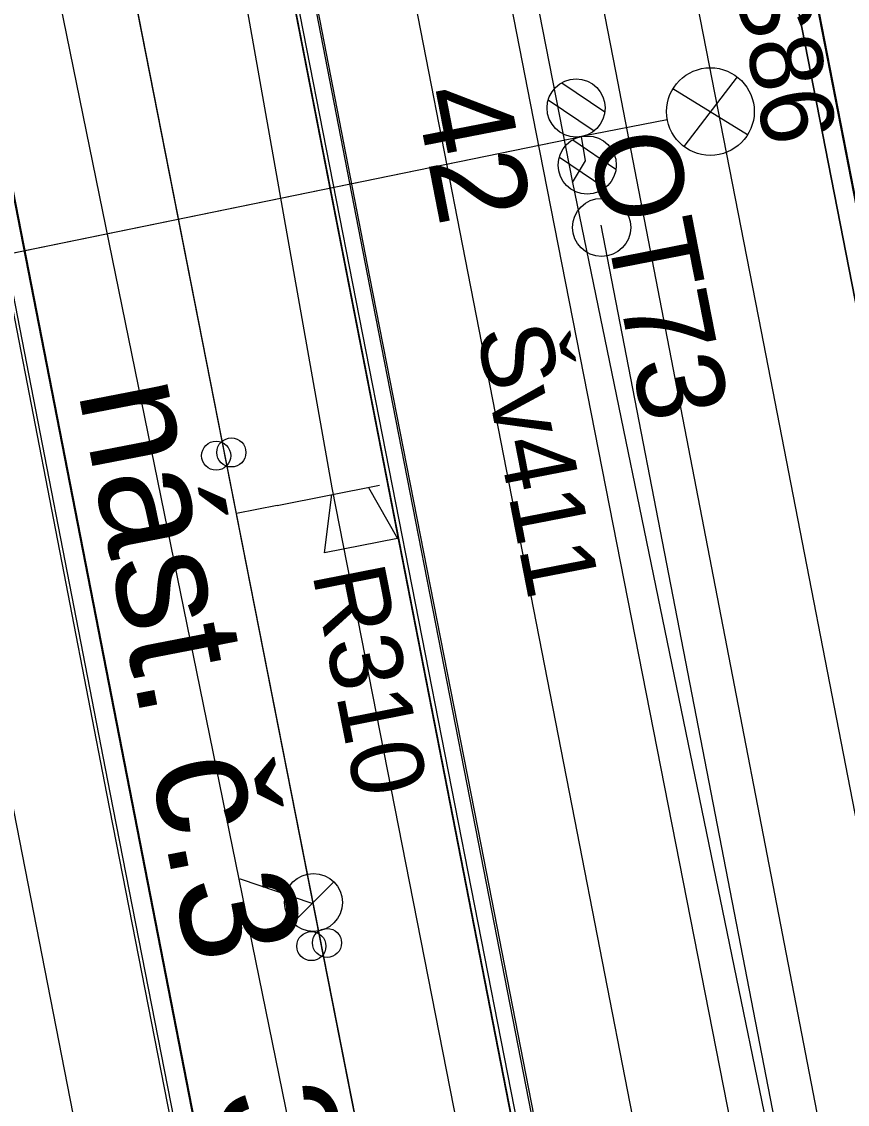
# Model space of a CAD drawing. Extents: x -545736 to -544888, y -1122892 to -1119128.
# Drawn here: x -545190.24 to -545176.05, y -1121835.11 to -1121816.49 of the extents above; entities that cross this region are included whole.
import ezdxf

# ---------------------------------------------------------------- set-up
doc = ezdxf.new("R2010")
doc.units = 0
for name, color, linetype in [('Podbarveni_Nastupiste', 7, 'Continuous'), ('Podbarveni_Zastreseni_Pozemni', 7, 'Continuous'), ('Vrstva 1 - Koleje', 7, 'Continuous'), ('Vrstva 11 - Trakce', 7, 'Continuous'), ('Vrstva 14_zastreseni a nastupiste', 7, 'Continuous'), ('Vrstva 16_plochy', 7, 'Continuous'), ('Vrstva 25', 7, 'Continuous'), ('Vrstva 26', 7, 'Continuous'), ('Vrstva 29 - sdelzar', 7, 'Continuous'), ('Vrstva 31', 7, 'Continuous'), ('Vrstva 33 - prvky sdelzar', 7, 'Continuous'), ('Vrstva 4 - Teren - stezky - prechody - plochy', 7, 'Continuous'), ('Vrstva 42', 7, 'Continuous'), ('Vrstva 43', 7, 'Continuous'), ('Vrstva 44', 7, 'Continuous')]:
    doc.layers.add(name, color=color, linetype=linetype)

msp = doc.modelspace()

# ---------------------------------------------------------------- linework, layer by layer
at = {"layer": 'Podbarveni_Nastupiste'}
for points in [[(-545217.368, -1121682.822), (-545215.446, -1121692.657), (-545213.545, -1121702.425), (-545211.641, -1121712.196), (-545209.721, -1121722.039), (-545207.816, -1121731.8), (-545205.906, -1121741.605), (-545203.994, -1121751.399), (-545202.093, -1121761.155), (-545200.179, -1121770.948), (-545198.277, -1121780.734), (-545196.359, -1121790.595), (-545195.979, -1121792.554), (-545194.455, -1121800.349), (-545192.535, -1121810.197), (-545190.626, -1121819.979), (-545188.728, -1121829.75), (-545186.804, -1121839.582), (-545184.9, -1121849.369), (-545182.993, -1121859.16)], [(-545176.664, -1121859.989), (-545178.574, -1121850.184), (-545180.481, -1121840.388), (-545182.39, -1121830.601), (-545184.299, -1121820.832), (-545186.202, -1121811.019), (-545188.114, -1121801.21), (-545190.028, -1121791.416), (-545191.936, -1121781.597), (-545194.23, -1121769.859), (-545195.758, -1121762.016), (-545197.67, -1121752.211), (-545199.585, -1121742.389), (-545201.492, -1121732.62), (-545203.329, -1121723.177), (-545205.298, -1121713.047), (-545207.216, -1121703.229), (-545209.127, -1121693.444), (-545211.033, -1121683.652)], [(-545187.331, -1121762.745), (-545185.417, -1121772.514), (-545183.504, -1121782.344), (-545181.6, -1121792.141), (-545179.691, -1121801.918), (-545177.789, -1121811.689), (-545175.868, -1121821.513), (-545173.955, -1121831.302)]]:
    msp.add_lwpolyline(points, dxfattribs=at)
at = {"layer": 'Podbarveni_Zastreseni_Pozemni'}
for points in [[(-545158.353, -1121955.704), (-545167.91, -1121906.688), (-545177.482, -1121857.6), (-545187.03, -1121808.63), (-545196.619, -1121759.457), (-545206.211, -1121710.262)], [(-545189.316, -1121750.748), (-545187.893, -1121758.049), (-545178.344, -1121807.045), (-545168.782, -1121856.109), (-545159.222, -1121905.16), (-545158.284, -1121909.972)], [(-545201.855, -1121760.601), (-545192.303, -1121809.6), (-545182.738, -1121858.66), (-545173.147, -1121907.858), (-545163.62, -1121956.724)]]:
    msp.add_lwpolyline(points, dxfattribs=at)
at = {"layer": 'Vrstva 1 - Koleje'}
for points in [[(-545204.598, -1121683.045), (-545202.446, -1121694.084), (-545200.893, -1121702.036), (-545198.518, -1121714.179), (-545196.602, -1121723.995), (-545194.695, -1121733.769), (-545192.79, -1121743.532), (-545190.869, -1121753.385), (-545188.974, -1121763.101), (-545187.053, -1121772.965), (-545185.151, -1121782.729), (-545183.231, -1121792.594), (-545181.323, -1121802.379), (-545179.426, -1121812.108), (-545177.532, -1121821.821), (-545175.608, -1121831.705), (-545173.691, -1121841.53), (-545171.796, -1121851.251), (-545169.872, -1121861.126)], [(-545219.01, -1121683.169), (-545217.101, -1121692.961), (-545215.17, -1121702.86), (-545213.27, -1121712.617), (-545211.361, -1121722.411), (-545209.465, -1121732.134), (-545207.557, -1121741.929), (-545205.641, -1121751.761), (-545203.736, -1121761.535), (-545201.841, -1121771.262), (-545199.933, -1121781.054), (-545197.636, -1121792.838), (-545196.098, -1121800.727), (-545194.176, -1121810.583), (-545192.282, -1121820.3), (-545190.374, -1121830.083), (-545188.448, -1121839.971), (-545186.548, -1121849.715), (-545184.635, -1121859.52)], [(-545209.393, -1121683.199), (-545207.488, -1121692.987), (-545205.563, -1121702.847), (-545203.658, -1121712.62), (-545201.742, -1121722.443), (-545199.842, -1121732.176), (-545197.931, -1121741.977), (-545196.019, -1121751.798), (-545194.112, -1121761.581), (-545192.212, -1121771.322), (-545190.282, -1121781.238), (-545188.375, -1121791.011), (-545186.47, -1121800.793), (-545184.553, -1121810.635), (-545182.663, -1121820.345), (-545180.739, -1121830.214), (-545178.835, -1121839.985), (-545176.93, -1121849.755), (-545175.02, -1121859.552)]]:
    msp.add_lwpolyline(points, dxfattribs=at)
at = {"layer": 'Vrstva 11 - Trakce'}
for p, q in [((-545180.957, -1121817.54), (-545180.217, -1121818.039)), ((-545181.189, -1121817.836), (-545180.403, -1121818.367)), ((-545208.457, -1121824.167), (-545180.616, -1121818.465)), ((-545180.769, -1121818.524), (-545180.026, -1121819.025)), ((-545180.999, -1121818.822), (-545180.215, -1121819.35))]:
    msp.add_line(p, q, dxfattribs=at)
for centre in [(-545180.711, -1121817.974), (-545180.521, -1121818.956)]:
    msp.add_circle(centre, 0.5, dxfattribs=at)
at = {"layer": 'Vrstva 14_zastreseni a nastupiste'}
for points in [[(-545217.421, -1121682.837), (-545215.499, -1121692.672), (-545213.598, -1121702.44), (-545211.694, -1121712.211), (-545209.774, -1121722.054), (-545207.869, -1121731.815), (-545205.959, -1121741.62), (-545204.047, -1121751.414), (-545202.146, -1121761.17), (-545200.232, -1121770.963), (-545198.33, -1121780.749), (-545196.412, -1121790.61), (-545196.032, -1121792.569), (-545194.508, -1121800.364), (-545192.588, -1121810.212), (-545190.679, -1121819.994), (-545188.781, -1121829.765), (-545186.857, -1121839.597), (-545184.953, -1121849.384), (-545183.046, -1121859.175)], [(-545217.368, -1121682.822), (-545215.446, -1121692.657), (-545213.545, -1121702.425), (-545211.641, -1121712.196), (-545209.721, -1121722.039), (-545207.816, -1121731.8), (-545205.906, -1121741.605), (-545203.994, -1121751.399), (-545202.093, -1121761.155), (-545200.179, -1121770.948), (-545198.277, -1121780.734), (-545196.359, -1121790.595), (-545195.979, -1121792.554), (-545194.455, -1121800.349), (-545192.535, -1121810.197), (-545190.626, -1121819.979), (-545188.728, -1121829.75), (-545186.804, -1121839.582), (-545184.9, -1121849.369), (-545182.993, -1121859.16)], [(-545176.664, -1121859.989), (-545178.574, -1121850.184), (-545180.481, -1121840.388), (-545182.39, -1121830.601), (-545184.299, -1121820.832), (-545186.202, -1121811.019), (-545188.114, -1121801.21), (-545190.028, -1121791.416), (-545191.936, -1121781.597), (-545194.23, -1121769.859), (-545195.758, -1121762.016), (-545197.67, -1121752.211), (-545199.585, -1121742.389), (-545201.492, -1121732.62), (-545203.329, -1121723.177), (-545205.298, -1121713.047), (-545207.216, -1121703.229), (-545209.127, -1121693.444), (-545211.033, -1121683.652)], [(-545176.62, -1121860.033), (-545178.53, -1121850.228), (-545180.437, -1121840.432), (-545182.346, -1121830.645), (-545184.255, -1121820.876), (-545186.158, -1121811.063), (-545188.07, -1121801.254), (-545189.984, -1121791.46), (-545191.892, -1121781.641), (-545194.186, -1121769.903), (-545195.714, -1121762.06), (-545197.626, -1121752.255), (-545199.541, -1121742.433), (-545201.448, -1121732.664), (-545203.285, -1121723.221), (-545205.254, -1121713.091), (-545207.172, -1121703.273), (-545209.083, -1121693.488), (-545210.989, -1121683.696)], [(-545206.211, -1121710.262), (-545196.619, -1121759.457), (-545187.03, -1121808.63), (-545177.482, -1121857.6), (-545167.91, -1121906.688), (-545158.353, -1121955.704)], [(-545158.353, -1121955.704), (-545167.959, -1121906.425), (-545177.532, -1121857.312), (-545187.064, -1121808.415), (-545196.682, -1121759.07), (-545206.197, -1121710.259)], [(-545211.47, -1121711.284), (-545201.855, -1121760.601), (-545192.303, -1121809.6), (-545182.738, -1121858.66), (-545173.147, -1121907.858), (-545163.62, -1121956.724), (-545163.626, -1121956.727), (-545173.205, -1121907.598), (-545182.779, -1121858.496), (-545192.361, -1121809.351), (-545201.935, -1121760.249), (-545211.481, -1121711.288)], [(-545168.235, -1121860.711), (-545170.146, -1121850.904), (-545172.046, -1121841.135), (-545173.955, -1121831.302), (-545175.868, -1121821.513), (-545177.789, -1121811.689), (-545179.691, -1121801.918), (-545181.6, -1121792.141), (-545183.504, -1121782.344), (-545185.417, -1121772.514), (-545187.331, -1121762.745), (-545189.242, -1121752.936), (-545191.158, -1121743.114)], [(-545168.235, -1121860.711), (-545170.146, -1121850.904), (-545172.046, -1121841.135), (-545173.955, -1121831.302), (-545175.868, -1121821.513), (-545177.789, -1121811.689), (-545179.691, -1121801.918), (-545181.6, -1121792.141), (-545183.504, -1121782.344), (-545185.417, -1121772.514), (-545187.331, -1121762.745), (-545189.242, -1121752.936), (-545191.158, -1121743.114)], [(-545158.29, -1121909.976), (-545159.275, -1121904.923), (-545168.857, -1121855.768), (-545178.402, -1121806.802), (-545187.951, -1121757.812), (-545189.328, -1121750.75)], [(-545189.316, -1121750.748), (-545187.893, -1121758.049), (-545178.344, -1121807.045), (-545168.782, -1121856.109), (-545159.222, -1121905.16), (-545158.284, -1121909.972)]]:
    msp.add_lwpolyline(points, dxfattribs=at)
for centre in [(-545186.899, -1121823.955), (-545186.637, -1121823.899), (-545184.993, -1121832.336), (-545185.262, -1121832.391)]:
    msp.add_circle(centre, 0.25, dxfattribs=at)
at = {"layer": 'Vrstva 16_plochy'}
for points in [[(-545217.368, -1121682.822), (-545215.446, -1121692.657), (-545213.545, -1121702.425), (-545211.641, -1121712.196), (-545209.721, -1121722.039), (-545207.816, -1121731.8), (-545205.906, -1121741.605), (-545203.994, -1121751.399), (-545202.093, -1121761.155), (-545200.179, -1121770.948), (-545198.277, -1121780.734), (-545196.359, -1121790.595), (-545195.979, -1121792.554), (-545194.455, -1121800.349), (-545192.535, -1121810.197), (-545190.626, -1121819.979), (-545188.728, -1121829.75), (-545186.804, -1121839.582), (-545184.9, -1121849.369), (-545182.993, -1121859.16)], [(-545176.664, -1121859.989), (-545178.574, -1121850.184), (-545180.481, -1121840.388), (-545182.39, -1121830.601), (-545184.299, -1121820.832), (-545186.202, -1121811.019), (-545188.114, -1121801.21), (-545190.028, -1121791.416), (-545191.936, -1121781.597), (-545194.23, -1121769.859), (-545195.758, -1121762.016), (-545197.67, -1121752.211), (-545199.585, -1121742.389), (-545201.492, -1121732.62), (-545203.329, -1121723.177), (-545205.298, -1121713.047), (-545207.216, -1121703.229), (-545209.127, -1121693.444), (-545211.033, -1121683.652)], [(-545168.235, -1121860.711), (-545170.146, -1121850.904), (-545172.046, -1121841.135), (-545173.955, -1121831.302), (-545175.868, -1121821.513), (-545177.789, -1121811.689), (-545179.691, -1121801.918), (-545181.6, -1121792.141), (-545183.504, -1121782.344), (-545185.417, -1121772.514), (-545187.331, -1121762.745), (-545189.242, -1121752.936), (-545191.158, -1121743.114)]]:
    msp.add_lwpolyline(points, dxfattribs=at)
at = {"layer": 'Vrstva 25'}
for p, q in [((-545177.944, -1121817.439), (-545178.857, -1121818.638)), ((-545177.765, -1121818.438), (-545179.049, -1121817.646)), ((-545179.144, -1121818.178), (-545180.616, -1121818.465))]:
    msp.add_line(p, q, dxfattribs=at)
msp.add_lwpolyline([(-545208.457, -1121824.167), (-545180.616, -1121818.465)], dxfattribs=at)
msp.add_circle((-545178.403, -1121818.036), 0.754, dxfattribs=at)
at = {"layer": 'Vrstva 26'}
for points in [[(-545192.594, -1121758.954), (-545187.356, -1121785.651), (-545180.774, -1121819.253), (-545180.549, -1121818.885), (-545180.616, -1121818.465)], [(-545180.774, -1121819.253), (-545176.726, -1121838.909), (-545176.709, -1121840.619), (-545172.02, -1121864.309), (-545171.72, -1121864.124), (-545171.744, -1121863.972), (-545171.826, -1121863.589), (-545171.826, -1121863.589)]]:
    msp.add_lwpolyline(points, dxfattribs=at)
at = {"layer": 'Vrstva 29 - sdelzar'}
msp.add_line((-545185.85, -1121824.81), (-545186.55, -1121824.95), dxfattribs=at)
for points in [[(-545161.23, -1121954.22), (-545161.32, -1121954.32), (-545161.96, -1121950.99), (-545166.14, -1121929.44), (-545169.48, -1121912.2), (-545172.98, -1121894.15), (-545175.25, -1121882.41), (-545176.61, -1121875.48), (-545179.9, -1121858.78), (-545183.24, -1121841.76), (-545186.55, -1121824.95), (-545189.52, -1121809.83), (-545189.53, -1121809.79), (-545193.1, -1121791.33), (-545195.35, -1121779.72), (-545196.68, -1121772.84), (-545200.02, -1121755.61), (-545203.25, -1121738.95), (-545206.49, -1121722.18), (-545208.31, -1121712.8), (-545208.32, -1121712.72)], [(-545176.77, -1121874.7), (-545188.39, -1121815.6), (-545196.86, -1121771.93)]]:
    msp.add_lwpolyline(points, dxfattribs=at)
at = {"layer": 'Vrstva 31'}
msp.add_lwpolyline([(-545170.61, -1121902.505), (-545169.83, -1121902.32), (-545169.8, -1121901.51), (-545169.011, -1121900.695), (-545173.164, -1121879.068), (-545180.354, -1121842.406), (-545185.455, -1121816.369), (-545187.73, -1121805.097), (-545192.507, -1121780.186), (-545194.432, -1121775.331), (-545195.406, -1121775.086)], dxfattribs=at)
at = {"layer": 'Vrstva 33 - prvky sdelzar'}
msp.add_line((-545185.85, -1121824.81), (-545184.092, -1121824.464), dxfattribs=at)
msp.add_lwpolyline([(-545184.28, -1121824.501), (-545183.781, -1121825.382), (-545185.037, -1121825.628), (-545184.908, -1121824.625)], dxfattribs=at)
at = {"layer": 'Vrstva 4 - Teren - stezky - prechody - plochy'}
for points in [[(-545217.421, -1121682.837), (-545215.499, -1121692.672), (-545213.598, -1121702.44), (-545211.694, -1121712.211), (-545209.774, -1121722.054), (-545207.869, -1121731.815), (-545205.959, -1121741.62), (-545204.047, -1121751.414), (-545202.146, -1121761.17), (-545200.232, -1121770.963), (-545198.33, -1121780.749), (-545196.412, -1121790.61), (-545196.032, -1121792.569), (-545194.508, -1121800.364), (-545192.588, -1121810.212), (-545190.679, -1121819.994), (-545188.781, -1121829.765), (-545186.857, -1121839.597), (-545184.953, -1121849.384), (-545183.046, -1121859.175)], [(-545176.62, -1121860.033), (-545178.53, -1121850.228), (-545180.437, -1121840.432), (-545182.346, -1121830.645), (-545184.255, -1121820.876), (-545186.158, -1121811.063), (-545188.07, -1121801.254), (-545189.984, -1121791.46), (-545191.892, -1121781.641), (-545194.186, -1121769.903), (-545195.714, -1121762.06), (-545197.626, -1121752.255), (-545199.541, -1121742.433), (-545201.448, -1121732.664), (-545203.285, -1121723.221), (-545205.254, -1121713.091), (-545207.172, -1121703.273), (-545209.083, -1121693.488), (-545210.989, -1121683.696)], [(-545146.11, -1122004.734), (-545145.37, -1122004.712), (-545146.573, -1121994.03), (-545148.01, -1121983.54), (-545148.508, -1121980.262), (-545148.842, -1121978.248), (-545150.866, -1121967.009), (-545156.33, -1121939.097), (-545168.64, -1121875.718), (-545175.381, -1121841.399), (-545180.031, -1121817.339), (-545184.955, -1121792.055), (-545193.253, -1121749.702), (-545199.085, -1121719.832), (-545202.547, -1121701.925)], [(-545146.11, -1122004.734), (-545147.669, -1121994.146), (-545149.368, -1121983.787), (-545152.408, -1121967.248), (-545157.762, -1121939.32), (-545170.037, -1121876.045), (-545176.72, -1121842.206), (-545181.396, -1121818.39), (-545186.868, -1121790.341), (-545194.851, -1121749.267), (-545200.506, -1121720.067), (-545204.102, -1121702.263)], [(-545191.158, -1121743.114), (-545189.242, -1121752.936), (-545187.331, -1121762.745), (-545185.417, -1121772.514), (-545183.504, -1121782.344), (-545181.6, -1121792.141), (-545179.691, -1121801.918), (-545177.789, -1121811.689), (-545175.868, -1121821.513), (-545173.955, -1121831.302), (-545172.046, -1121841.135), (-545170.146, -1121850.904), (-545168.235, -1121860.711)]]:
    msp.add_lwpolyline(points, dxfattribs=at)
at = {"layer": 'Vrstva 42'}
msp.add_lwpolyline([(-545203.534, -1121918.02), (-545198.847, -1121917.36), (-545185.567, -1121915.086), (-545176.946, -1121913.531), (-545167.572, -1121911.811), (-545169.511, -1121901.523), (-545169.772, -1121900.147), (-545173.971, -1121879.393), (-545174.091, -1121878.805), (-545174.196, -1121878.05), (-545174.272, -1121877.624), (-545174.386, -1121877.061), (-545179.482, -1121851.396), (-545181.349, -1121842.633), (-545184.905, -1121824.51), (-545186.898, -1121813.243), (-545186.931, -1121810.892), (-545187.672, -1121807.861)], dxfattribs=at)
at = {"layer": 'Vrstva 43'}
msp.add_line((-545185.579, -1121831.991), (-545184.874, -1121831.287), dxfattribs=at)
for centre, radius in [((-545180.273, -1121820.028), 0.5), ((-545185.226, -1121831.64), 0.498)]:
    msp.add_circle(centre, radius, dxfattribs=at)
at = {"layer": 'Vrstva 44'}
for points in [[(-545191.555, -1121799.358), (-545191.426, -1121799.41), (-545192.815, -1121799.846), (-545192.854, -1121801.099), (-545190.114, -1121814.291), (-545189.96, -1121814.512), (-545189.86, -1121814.806), (-545186.511, -1121831.238), (-545183.538, -1121845.823), (-545183.49, -1121846.087)], [(-545180.284, -1121819.992), (-545175.595, -1121844.212), (-545175.609, -1121844.512)], [(-545186.511, -1121831.238), (-545186.487, -1121831.233), (-545185.257, -1121831.651), (-545185.227, -1121831.639)]]:
    msp.add_lwpolyline(points, dxfattribs=at)

# ---------------------------------------------------------------- texts
at = {"layer": 'Vrstva 11 - Trakce'}
msp.add_text('42', height=1.6, rotation=281.0001, dxfattribs=at).set_placement((-545183.488, -1121817.713))
at = {"layer": 'Vrstva 14_zastreseni a nastupiste'}
msp.add_text('nást. č.3   395m', height=2, rotation=280.9927, dxfattribs=at).set_placement((-545189.277, -1121822.842))
at = {"layer": 'Vrstva 25'}
msp.add_text('OT73', height=1.5, rotation=281.0828, dxfattribs=at).set_placement((-545180.504, -1121818.521))
at = {"layer": 'Vrstva 33 - prvky sdelzar'}
msp.add_text('R310', height=1.25, rotation=281.1247, dxfattribs=at).set_placement((-545185.251, -1121825.974))
at = {"layer": 'Vrstva 43'}
for s, rotation, p in [('Š86', 281.0281, (-545178.01, -1121815.757)), ('Šv411', 281.0323, (-545182.428, -1121821.807))]:
    msp.add_text(s, height=1.25, rotation=rotation, dxfattribs=at).set_placement(p)

doc.saveas('drawing.dxf')
